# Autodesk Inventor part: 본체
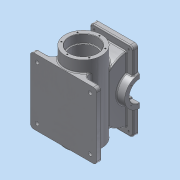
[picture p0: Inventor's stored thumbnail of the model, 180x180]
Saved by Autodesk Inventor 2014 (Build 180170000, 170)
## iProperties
Created: 2023-07
Part Number: 본체
Material: 알루미늄 6061
Document SubType Name: Modeling
Designer: dg
Density: 2.71 g/cm^3
Appearance: 알루미늄 - 평지
Mass: 5812.73 g
Surface Area: 2854.98 cm^2
Volume: 2144.92 cm^3
Author: dg
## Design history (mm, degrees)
sketch "스케치4"
  geometry: C1 r 55 at (0, 0); 1 further point
  constraints: 1 centre point, 1 coincident
  dimensions: "d13" = 110 diameter of C1
extrude "돌출4" new body sketch "스케치4" distance "d14" = 242; taper "d15" = 0 deg
sketch "스케치5"
  geometry: L1 (55, 242)-(-55, 242) reference; L2 (-55, 0)-(55, 0) reference; L3 (55, 242)-(55, 0) reference; L4 (55, 0)-(-55, 0) reference; L5 (-55, 0)-(-55, 242) reference; L6 (-55, 242)-(55, 242) reference; L7 (100, 107)-(100, 7); L8 (100, 107)-(100, 207); A1 r 100 centre (100, 107) between (100, 7) and (100, 207); 1 further point
  constraints: 4 end point, 2 point on circle, 1 centre point, 1 collinear, 1 perpendicular
  dimensions: "d18" = 107 distance from line of L7.start L2; "d20" = 155 distance from line of L5 L7.start; "d21" = 200 diameter of A1
  node "투영된 루프1"
  node "절단 모서리 투영1"
extrude "돌출5" join sketch "스케치5" stored distance "d22" = 90; taper "d23" = 0 deg
sketch "스케치6"
  geometry: L1 (0, 0)-(0, 200) reference; L2 (-20, 220)-(110, 220); L3 (110, 220)-(110, -20); L4 (110, -20)-(-20, -20); L5 (-20, -20)-(-20, 220); 4 further points
  constraints: 8 end point, 3 midpoint, 2 parallel, 1 horizontal, 1 horizontal alignment, 1 perpendicular, 1 vertical alignment
  dimensions: "d24" = 130 distance of L2.start L2.end; "d25" = 240 distance of L4.end L2.start
extrude "돌출6" join sketch "스케치6" distance "d26" = 15; taper "d27" = 0 deg
node "작업 평면2"
sketch "스케치7"
  geometry: L1 (242, -55)-(0, -55) reference; L2 (0, -55)-(0, 55) reference; L3 (0, 55)-(17.697, 55) reference; L4 (8.131, 85)-(-13, 85) reference; L5 (-13, 85)-(-13, 100) reference; L6 (-13, 100)-(227, 100) reference; L7 (227, 100)-(227, 85) reference; L8 (227, 85)-(205.869, 85) reference; L9 (196.303, 55)-(242, 55) reference; L10 (242, 55)-(242, -55) reference; L11 (227, 100)-(-13, 100) reference; C1 r 87 at (107, 100); A1 r 100 centre (107, 100) between (8.131, 85) and (17.697, 55) reference; A2 r 100 centre (107, 100) between (196.303, 55) and (205.869, 85) reference; 2 further points
  constraints: 2 coincident, 1 centre point, 1 midpoint
  dimensions: "d29" = 174 diameter of C1
  node "절단 모서리 투영2"
extrude "돌출7" cut sketch "스케치7" stored distance "d30" = 64; taper "d31" = 0 deg
node "작업 평면3"
sketch "스케치8"
  geometry: L1 (240, 0)-(0, 0) reference; L2 (0, 0)-(0, -15) reference; L3 (240, -15)-(0, -15) reference; L4 (240, 0)-(240, -15) reference; L5 (218.869, -15)-(21.131, -15) reference; L6 (192.97, -68.377)-(47.03, -68.377) reference; L7 (75, 0)-(165, 0); A1 r 100 centre (120, 0) between (21.131, -15) and (47.03, -68.377) reference; A2 r 100 centre (120, 0) between (192.97, -68.377) and (218.869, -15) reference; A3 r 45 centre (120, 0) between (75, 0) and (165, 0); 1 further point
  constraints: 2 end point, 2 point on circle, 2 point on line, 1 centre point, 1 coincident
  dimensions: "d33" = 90 diameter of A3
extrude "돌출8" join sketch "스케치8" stored distance "d34" = 64; taper "d35" = 0 deg
sketch "스케치9"
  geometry: C1 r 31 at (120, 0); A1 r 45 centre (120, 0) between (75, 0) and (165, 0) reference; 1 further point
  constraints: 1 centre point, 1 coincident
  dimensions: "d36" = 62 diameter of C1
extrude "돌출9" cut sketch "스케치9" distance "d37" = 23; taper "d38" = 0 deg
sketch "스케치10"
  geometry: C1 r 27.5 at (120, 0); A1 r 31 centre (120, 0) between (89, 0) and (151, 0) reference; 1 further point
  constraints: 1 centre point, 1 coincident
  dimensions: "d39" = 55 diameter of C1
extrude "돌출10" cut sketch "스케치10" distance "d40" = 23; taper "d41" = 0 deg
sketch "스케치11"
  geometry: C1 r 55 at (0, 0) reference; C2 r 42.5 at (0, 0)
  constraints: 1 centre point, 1 coincident
  dimensions: "d42" = 85 diameter of C2
extrude "돌출11" cut sketch "스케치11" distance "d43" = 25; taper "d44" = 0 deg
sketch "스케치12"
  geometry: C1 r 55 at (0, 0) reference; 1 further point
  constraints: 1 coincident
hole "구멍1" sketch "스케치12" at (0, 0) diameter "d45" = 77; stored, may be unused: countersink angle "d49" = 90 deg, drill point angle "d51" = 0 deg; dims "d46" = 6, "d47" = 85, "d48" = 25, "d50" = 8
fillet "모깎기1" dims "d52" = 1.1
node "작업 평면4"
node "작업 평면7"
sketch "스케치14"
  geometry: L1 (-100, -45)-(100, -45); L2 (100, -45)-(100, -60); L3 (100, -60)-(-100, -60); L4 (-100, -60)-(-100, -45); 2 further points
  constraints: 8 end point, 2 parallel, 1 horizontal, 1 midpoint, 1 perpendicular, 1 vertical alignment
  dimensions: "d59" = 200 distance of L2.end L3.end; "d60" = 60 distance from line of L3 point (0, 0); "d61" = 15 distance of L1.end L2.end
extrude "돌출12" join sketch "스케치14" distance "d62" = 200; taper "d63" = 0 deg
sketch "스케치15"
  geometry: L1 (-63.246, 200)-(-63.246, 0) reference; L2 (-131.623, 200)-(-63.246, 200) reference; L3 (-131.623, 0)-(-131.623, 200) reference; L4 (-131.623, 0)-(-63.246, 0) reference; 5 further points
  constraints: 2 horizontal alignment, 2 vertical alignment
  dimensions: "d64" = 160 distance of point (48.377, 180) point (-111.623, 180); "d65" = 160 distance of point (-111.623, 20) point (-111.623, 180); "d66" = 20 distance from line of L3 point (-111.623, 180); "d67" = 20 distance from line of L2 point (-111.623, 180)
hole "구멍2" sketch "스케치15" at (-111.623, 180), (-111.623, 20), (48.377, 20), (48.377, 180) diameter "d68" = 11; stored, may be unused: countersink angle "d72" = 90 deg, drill point angle "d74" = 0 deg; dims "d69" = 6, "d70" = 28, "d71" = 2, "d73" = 8
fillet "모깎기2" dims "d75" = 15
fillet "모깎기3" dims "d76" = 10
fillet "모깎기4" dims "d77" = 3
fillet "모깎기5" dims "d78" = 3
fillet "모깎기6" dims "d79" = 3
chamfer "모따기1" distance "d80" = 1; stored, may be unused: second distance "d81" = 2, angle "d82" = 45 deg
chamfer "모따기2" distance "d83" = 1; stored, may be unused: second distance "d84" = 2, angle "d85" = 45 deg
chamfer "모따기3" distance "d86" = 1; stored, may be unused: second distance "d87" = 2, angle "d88" = 45 deg
fillet "모깎기7" dims "d89" = 10
fillet "모깎기8" dims "d90" = 3
fillet "모깎기9" dims "d91" = 3
sketch "스케치16"
  geometry: L1 (-7, 7)-(-7, 187) reference; L2 (-10, 187)-(-10, 7) reference; 3 further points
  constraints: 1 horizontal alignment, 1 midpoint, 1 other
  dimensions: "d92" = 15 distance from line of L2 point (5, 97)
feature "엠보싱1" sketch "스케치16" dims "d93" = 0.5, "d94" = 0
sketch "스케치17"
  geometry: L1 (120, 0)-(120, -45); L2 (120, 0)-(151.82, -31.82); L3 (120, 0)-(88.18, -31.82); A1 r 45 centre (120, 0) between (75, 0) and (165, 0) reference; A2 r 37 centre (120, 0) between (93.837, -26.163) and (146.163, -26.163); 1 further point
  constraints: 6 end point, 5 point on circle, 2 point on line, 1 centre point, 1 coincident
  dimensions: "d95" = 45 deg angle of L1 L3; "d96" = 45 deg angle of L2 L1; "d97" = 74 diameter of A2
hole "구멍3" sketch "스케치17" at (93.837, -26.163), (146.163, -26.163) diameter "d98" = 4.134; stored, may be unused: countersink angle "d102" = 90 deg, drill point angle "d104" = 118 deg; dims "d99" = 10, "d100" = 28, "d101" = 2, "d103" = 12
sketch "스케치18"
  geometry: C1 r 55 at (0, 0) reference; 1 further point
  constraints: 1 vertical alignment
  dimensions: "d107" = 48.5 distance of C1.centre point (0, 48.5)
hole "구멍4" sketch "스케치18" at (0, 48.5) diameter "d108" = 4.134; stored, may be unused: countersink angle "d112" = 90 deg, drill point angle "d114" = 118 deg; dims "d109" = 10, "d110" = 28, "d111" = 2, "d113" = 12
sketch "스케치19"
  geometry: C1 r 55 at (0, 0) reference; 1 further point
  constraints: 1 vertical alignment
  dimensions: "d118" = 48.5 distance of C1.centre point (0, 48.5)
hole "구멍5" sketch "스케치19" at (0, 48.5) diameter "d119" = 4.134; stored, may be unused: countersink angle "d123" = 90 deg, drill point angle "d125" = 118 deg; dims "d120" = 10, "d121" = 28, "d122" = 2, "d124" = 12
fillet "모깎기12" dims "d136" = 3
fillet "모깎기13" dims "d137" = 3
fillet "모깎기14" dims "d138" = 3
fillet "모깎기15" dims "d139" = 1
sketch "스케치22"
  geometry: L1 (-23, 59.5)-(-23, -4.5) reference; L2 (-23, 72.5)-(-23, -17.5) reference; 7 further points
  constraints: 2 horizontal alignment, 2 midpoint, 2 vertical alignment, 1 coincident
  dimensions: "d151" = 104 distance of point (99, -79.5) point (-5, -79.5); "d152" = 52 horizontal distance of point (47, 134.5) point (-5, -79.5) (= 0.5 x d151); "d153" = 214 distance of point (-5, -79.5) point (-5, 134.5); "d154" = 107 vertical distance of point (-23, 27.5) point (-5, -79.5) (= 0.5 x d153)
hole "구멍8" sketch "스케치22" at (-5, -79.5), (99, -79.5), (-5, 134.5), (99, 134.5) diameter "d155" = 4.917; stored, may be unused: countersink angle "d159" = 90 deg, drill point angle "d161" = 118 deg; dims "d156" = 15, "d157" = 4, "d158" = 2, "d160" = 20
node "솔리드2"
mirror "대칭1"
mirror "대칭2"
mirror "대칭3"
pattern_circular "원형 패턴1" dims angle "d116" = 360 deg
pattern_circular "원형 패턴2" dims angle "d127" = 360 deg
node "투영된 루프2"
node "투영된 루프3"
node "투영된 루프4"
other parameters: "d28" = -45, "d32" = 5, "d58" = -35
